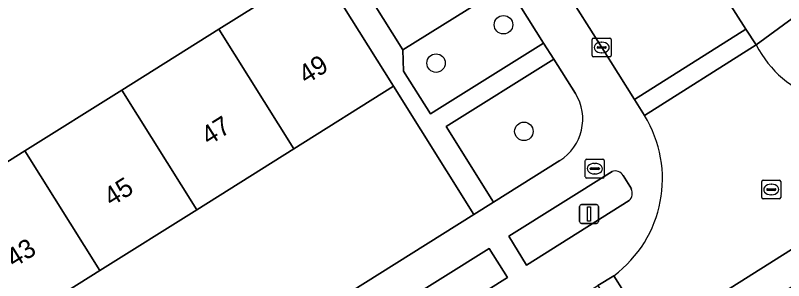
# Model space of a CAD drawing. Extents: x 160077 to 160948, y 386481 to 387498.
# Drawn here: x 160443.45 to 160484.07, y 387235.45 to 387249.48 of the extents above; entities that cross this region are included whole.
import ezdxf

# ---------------------------------------------------------------- set-up
doc = ezdxf.new("R2010")
doc.units = 0
for name, color, linetype in [('IMGEO_Boom', 7, 'Continuous'), ('IMGEO_Brandkraan', 7, 'Continuous'), ('IMGEO_Erf', 7, 'Continuous'), ('IMGEO_Groenvoorziening', 7, 'Continuous'), ('IMGEO_Kolk', 7, 'Continuous'), ('IMGEO_Lichtmast', 7, 'Continuous'), ('IMGEO_Pand', 7, 'Continuous'), ('IMGEO_Pand_nummerreeks', 7, 'Continuous'), ('IMGEO_Rijbaan_lokaal_gesloten', 7, 'Continuous'), ('IMGEO_Rijbaan_lokaal_open', 7, 'Continuous'), ('IMGEO_Rioolput', 7, 'Continuous'), ('IMGEO_Voetpad_open', 7, 'Continuous')]:
    doc.layers.add(name, color=color, linetype=linetype)

msp = doc.modelspace()

# ---------------------------------------------------------------- linework, layer by layer
at = {"layer": 'IMGEO_Boom'}
for centre in [(160469.256, 387248.98), (160465.692, 387246.952), (160470.336, 387243.344)]:
    msp.add_circle(centre, 0.489, dxfattribs=at)
at = {"layer": 'IMGEO_Brandkraan'}
for p, q in [((160473.583, 387240.946), (160473.583, 387241.798)), ((160473.658, 387241.872), (160474.51, 387241.872)), ((160474.071, 387241.652), (160474.096, 387241.652)), ((160474.584, 387241.798), (160474.584, 387240.946)), ((160473.842, 387241.366), (160473.842, 387241.378)), ((160474.28, 387241.329), (160473.882, 387241.329)), ((160473.885, 387241.415), (160474.283, 387241.415)), ((160474.326, 387241.378), (160474.326, 387241.366)), ((160474.51, 387240.872), (160473.658, 387240.872)), ((160474.094, 387241.092), (160474.069, 387241.092))]:
    msp.add_line(p, q, dxfattribs=at)
for points in [[(160473.583, 387240.946), (160473.583, 387241.798)], [(160473.658, 387241.872), (160474.51, 387241.872)], [(160474.584, 387241.798), (160474.584, 387240.946)], [(160474.51, 387240.872), (160473.658, 387240.872)]]:
    msp.add_lwpolyline(points, dxfattribs=at)
for centre, radius, start, end in [((160473.66, 387241.796), 0.0765, 91.552, 178.448), ((160473.66, 387241.796), 0.0765, 91.552, 178.448), ((160474.508, 387241.796), 0.0765, 1.552, 88.448), ((160474.508, 387241.796), 0.0765, 1.552, 88.448), ((160473.882, 387241.375), 0.0403, 85.8775, 175.7526), ((160473.879, 387241.365), 0.0366, 178.938, 274.7102), ((160474.283, 387241.372), 0.043, 264.8664, 352.4533), ((160474.287, 387241.377), 0.0386, 1.7309, 96.639), ((160473.66, 387240.948), 0.0765, 181.552, 268.448), ((160473.66, 387240.948), 0.0765, 181.552, 268.448), ((160474.508, 387240.948), 0.0765, 271.552, 358.448), ((160474.508, 387240.948), 0.0765, 271.552, 358.448)]:
    msp.add_arc(centre, radius, start, end, dxfattribs=at)
for centre, major_axis, ratio, start_param, end_param in [((160474.07, 387241.372), (-0.387, 0.002), 0.722429, 4.712389, 7.853982), ((160474.095, 387241.372), (-0.39, 0.002), 0.717154, 1.570796, 4.712389)]:
    msp.add_ellipse(centre, major_axis=major_axis, ratio=ratio, start_param=start_param, end_param=end_param, dxfattribs=at)
at = {"layer": 'IMGEO_Erf'}
for points in [[(160438.821, 387239.091), (160443.947, 387242.308), (160449.074, 387245.524), (160454.2, 387248.74), (160456.208, 387250), (160459.474, 387252.049), (160452.689, 387262.566), (160451.218, 387261.627), (160452.547, 387259.544), (160448.888, 387257.207), (160445.303, 387254.918), (160443.973, 387257.001), (160443.921, 387257.082), (160440.965, 387255.195)], [(160467.691, 387238.95), (160463.439, 387245.729), (160458.165, 387242.42), (160453.038, 387239.204), (160447.912, 387235.987), (160442.785, 387232.771), (160437.658, 387229.555), (160432.533, 387226.339), (160427.406, 387223.123), (160422.279, 387219.906), (160417.152, 387216.69), (160412.026, 387213.474), (160406.899, 387210.257), (160401.625, 387206.948), (160405.127, 387201.741)], [(160407.555, 387201.225), (160467.691, 387238.95)]]:
    msp.add_lwpolyline(points, dxfattribs=at)
at = {"layer": 'IMGEO_Groenvoorziening'}
for points in [[(160470.126, 387250), (160469.44, 387251.093), (160463.936, 387247.648), (160463.974, 387246.534), (160465.393, 387244.266), (160465.867, 387244.563), (160471.376, 387248.01)], [(160463.592, 387234.087), (160464.554, 387232.533), (160469.465, 387235.624), (160468.507, 387237.153)]]:
    msp.add_lwpolyline(points, close=True, dxfattribs=at)
for points in [[(160473.058, 387245.353), (160471.912, 387247.163), (160466.226, 387243.596), (160468.731, 387239.603), (160472.236, 387241.799)], [(160474.996, 387241.227), (160469.541, 387237.805)], [(160476.016, 387240.304), (160475.578, 387241.007)], [(160469.541, 387237.805), (160470.478, 387236.277), (160475.903, 387239.682)]]:
    msp.add_lwpolyline(points, dxfattribs=at)
for centre, radius, start, end in [((160470.863, 387243.989), 2.584, 302.0876, 31.8667), ((160475.154, 387240.764), 0.489, 29.7528, 108.8333), ((160475.516, 387240.074), 0.55, 314.6481, 24.7584)]:
    msp.add_arc(centre, radius, start, end, dxfattribs=at)
at = {"layer": 'IMGEO_Kolk'}
for p, q in [((160473.948, 387247.35), (160473.948, 387248.202)), ((160474.023, 387248.276), (160474.875, 387248.276)), ((160474.436, 387248.056), (160474.461, 387248.056)), ((160474.949, 387248.202), (160474.949, 387247.35)), ((160474.207, 387247.77), (160474.207, 387247.782)), ((160474.645, 387247.733), (160474.247, 387247.733)), ((160474.25, 387247.819), (160474.648, 387247.819)), ((160474.691, 387247.782), (160474.691, 387247.77)), ((160474.875, 387247.276), (160474.023, 387247.276)), ((160474.459, 387247.496), (160474.434, 387247.496))]:
    msp.add_line(p, q, dxfattribs=at)
for points in [[(160473.948, 387247.35), (160473.948, 387248.202)], [(160474.023, 387248.276), (160474.875, 387248.276)], [(160474.949, 387248.202), (160474.949, 387247.35)], [(160474.875, 387247.276), (160474.023, 387247.276)]]:
    msp.add_lwpolyline(points, dxfattribs=at)
for centre, radius, start, end in [((160474.025, 387248.2), 0.0765, 91.552, 178.448), ((160474.025, 387248.2), 0.0765, 91.552, 178.448), ((160474.873, 387248.2), 0.0765, 1.552, 88.448), ((160474.873, 387248.2), 0.0765, 1.552, 88.448), ((160474.247, 387247.779), 0.0403, 85.8775, 175.7526), ((160474.244, 387247.769), 0.0366, 178.938, 274.7102), ((160474.648, 387247.776), 0.043, 264.8664, 352.4533), ((160474.652, 387247.781), 0.0386, 1.7309, 96.639), ((160474.025, 387247.352), 0.0765, 181.552, 268.448), ((160474.025, 387247.352), 0.0765, 181.552, 268.448), ((160474.873, 387247.352), 0.0765, 271.552, 358.448), ((160474.873, 387247.352), 0.0765, 271.552, 358.448)]:
    msp.add_arc(centre, radius, start, end, dxfattribs=at)
for centre, major_axis, ratio, start_param, end_param in [((160474.435, 387247.776), (-0.387, 0.002), 0.722429, 4.712389, 7.853982), ((160474.46, 387247.776), (-0.39, 0.002), 0.717154, 1.570796, 4.712389)]:
    msp.add_ellipse(centre, major_axis=major_axis, ratio=ratio, start_param=start_param, end_param=end_param, dxfattribs=at)
at = {"layer": 'IMGEO_Lichtmast'}
for p, q in [((160473.281, 387238.575), (160473.281, 387239.375)), ((160473.281, 387239.375), (160473.281, 387238.575)), ((160473.381, 387239.475), (160474.171, 387239.475)), ((160474.171, 387239.475), (160473.381, 387239.475)), ((160474.271, 387239.375), (160474.271, 387238.575)), ((160474.271, 387238.575), (160474.271, 387239.375)), ((160474.171, 387238.475), (160473.381, 387238.475)), ((160473.381, 387238.475), (160474.171, 387238.475))]:
    msp.add_line(p, q, dxfattribs=at)
msp.add_lwpolyline([(160473.701, 387239.35), (160473.851, 387239.35), (160473.851, 387238.6), (160473.701, 387238.6), (160473.701, 387239.35)], dxfattribs=at)
for centre, start, end in [((160473.381, 387239.375), 90, 180), ((160473.381, 387239.375), 90, 180), ((160474.171, 387239.375), 0, 90), ((160474.171, 387239.375), 360, 90), ((160473.381, 387238.575), 180, 270), ((160473.381, 387238.575), 180, 270), ((160474.171, 387238.575), 270, 0), ((160474.171, 387238.575), 270, 0)]:
    msp.add_arc(centre, 0.1, start, end, dxfattribs=at)
at = {"layer": 'IMGEO_Pand'}
for points in [[(160469.44, 387251.093), (160469.313, 387251.296), (160467.838, 387253.653), (160462.334, 387250.208), (160463.936, 387247.648)], [(160458.165, 387242.42), (160463.439, 387245.729), (160460.76, 387250), (160459.474, 387252.049), (160456.208, 387250), (160454.2, 387248.74)], [(160454.2, 387248.74), (160449.074, 387245.524), (160453.038, 387239.204), (160458.165, 387242.42)], [(160447.912, 387235.987), (160453.038, 387239.204), (160449.074, 387245.524), (160443.947, 387242.308)], [(160443.947, 387242.308), (160438.821, 387239.091), (160442.785, 387232.771), (160447.912, 387235.987)]]:
    msp.add_lwpolyline(points, close=True, dxfattribs=at)
at = {"layer": 'IMGEO_Rijbaan_lokaal_gesloten'}
msp.add_lwpolyline([(160493.712, 387240.972), (160492.831, 387242.374), (160477.128, 387232.473), (160478.021, 387231.045)], close=True, dxfattribs=at)
at = {"layer": 'IMGEO_Rijbaan_lokaal_open'}
for points in [[(160454.544, 387279.719), (160463.8, 387264.904), (160472.539, 387250.825), (160474.449, 387247.776), (160476.176, 387245.021), (160482.077, 387248.744), (160480.89, 387250.608), (160479.886, 387252.225), (160472.444, 387264.366), (160463.176, 387278.973)], [(160482.621, 387247.91), (160476.71, 387244.182)], [(160475.088, 387235.715), (160477.128, 387232.473), (160492.831, 387242.374)]]:
    msp.add_lwpolyline(points, dxfattribs=at)
for points in [[(160482.621, 387247.91), (160482.077, 387248.744), (160476.176, 387245.021), (160476.71, 387244.182)], [(160475.088, 387235.715), (160474.253, 387235.192), (160475.133, 387233.755), (160476.287, 387231.935), (160477.162, 387230.526), (160478.021, 387231.045), (160477.128, 387232.473)]]:
    msp.add_lwpolyline(points, close=True, dxfattribs=at)
for centre, radius, start, end in [((160487.8, 387250.574), 5.824, 207.2196, 294.4722), ((160471.277, 387240.834), 6.382, 306.667, 31.6437)]:
    msp.add_arc(centre, radius, start, end, dxfattribs=at)
at = {"layer": 'IMGEO_Rioolput'}
for p, q in [((160482.988, 387240.769), (160483.84, 387240.769)), ((160482.913, 387239.843), (160482.913, 387240.695)), ((160483.401, 387240.549), (160483.426, 387240.549)), ((160483.914, 387240.695), (160483.914, 387239.843)), ((160483.172, 387240.263), (160483.172, 387240.275)), ((160483.61, 387240.226), (160483.212, 387240.226)), ((160483.215, 387240.312), (160483.613, 387240.312)), ((160483.424, 387239.989), (160483.399, 387239.989)), ((160483.656, 387240.275), (160483.656, 387240.263)), ((160483.84, 387239.769), (160482.988, 387239.769))]:
    msp.add_line(p, q, dxfattribs=at)
for points in [[(160482.988, 387240.769), (160483.84, 387240.769)], [(160482.913, 387239.843), (160482.913, 387240.695)], [(160483.914, 387240.695), (160483.914, 387239.843)], [(160483.84, 387239.769), (160482.988, 387239.769)]]:
    msp.add_lwpolyline(points, dxfattribs=at)
for centre, radius, start, end in [((160482.99, 387240.693), 0.0765, 91.552, 178.448), ((160482.99, 387240.693), 0.0765, 91.552, 178.448), ((160483.838, 387240.693), 0.0765, 1.552, 88.448), ((160483.838, 387240.693), 0.0765, 1.552, 88.448), ((160483.212, 387240.272), 0.0403, 85.8775, 175.7526), ((160483.209, 387240.262), 0.0366, 178.938, 274.7102), ((160483.613, 387240.269), 0.043, 264.8664, 352.4533), ((160483.617, 387240.274), 0.0386, 1.7309, 96.639), ((160482.99, 387239.845), 0.0765, 181.552, 268.448), ((160482.99, 387239.845), 0.0765, 181.552, 268.448), ((160483.838, 387239.845), 0.0765, 271.552, 358.448), ((160483.838, 387239.845), 0.0765, 271.552, 358.448)]:
    msp.add_arc(centre, radius, start, end, dxfattribs=at)
for centre, major_axis, ratio, start_param, end_param in [((160483.4, 387240.269), (-0.387, 0.002), 0.722429, 4.712389, 7.853982), ((160483.425, 387240.269), (-0.39, 0.002), 0.717154, 1.570796, 4.712389)]:
    msp.add_ellipse(centre, major_axis=major_axis, ratio=ratio, start_param=start_param, end_param=end_param, dxfattribs=at)
at = {"layer": 'IMGEO_Voetpad_open'}
for points in [[(160541.743, 387279.343), (160539.541, 387284.099), (160537.91, 387283.142), (160537.818, 387283.286), (160536.831, 387282.662), (160500, 387259.367), (160487.15, 387251.24), (160482.621, 387247.91)], [(160463.176, 387278.973), (160472.444, 387264.366), (160479.886, 387252.225), (160480.89, 387250.608), (160482.077, 387248.744), (160482.621, 387247.91), (160487.15, 387251.24)], [(160469.808, 387251.56), (160469.313, 387251.296), (160469.44, 387251.093), (160470.126, 387250), (160471.376, 387248.01), (160471.912, 387247.163), (160473.058, 387245.353)], [(160476.71, 387244.182), (160476.176, 387245.021), (160474.449, 387247.776), (160472.539, 387250.825)], [(160460.76, 387250), (160463.439, 387245.729), (160467.691, 387238.95), (160468.731, 387239.603), (160466.226, 387243.596), (160471.912, 387247.163), (160471.376, 387248.01), (160465.867, 387244.563), (160465.393, 387244.266), (160463.974, 387246.534), (160463.936, 387247.648), (160462.334, 387250.208)], [(160472.236, 387241.799), (160468.731, 387239.603), (160467.691, 387238.95), (160407.555, 387201.225), (160403.123, 387197.94), (160403.384, 387197.523)], [(160469.541, 387237.805), (160474.996, 387241.227)], [(160475.578, 387241.007), (160476.016, 387240.304)], [(160475.903, 387239.682), (160470.478, 387236.277), (160469.541, 387237.805)], [(160473.384, 387234.655), (160474.253, 387235.192), (160475.088, 387235.715)]]:
    msp.add_lwpolyline(points, dxfattribs=at)
msp.add_lwpolyline([(160468.507, 387237.153), (160469.465, 387235.624), (160464.554, 387232.533), (160463.592, 387234.087)], close=True, dxfattribs=at)
for centre, radius, start, end in [((160487.8, 387250.574), 5.824, 207.2196, 294.4722), ((160470.863, 387243.989), 2.584, 302.0876, 31.8667), ((160471.277, 387240.834), 6.382, 306.667, 31.6437), ((160475.154, 387240.764), 0.489, 29.7528, 108.8333), ((160475.516, 387240.074), 0.55, 314.6481, 24.7584)]:
    msp.add_arc(centre, radius, start, end, dxfattribs=at)

# ---------------------------------------------------------------- texts
at = {"layer": 'IMGEO_Pand_nummerreeks'}
for s, p in [('49', (160458.824, 387245.809)), ('47', (160453.673, 387242.577)), ('45', (160448.522, 387239.345)), ('43', (160443.371, 387236.113))]:
    msp.add_text(s, height=1, rotation=32.1034, dxfattribs=at).set_placement(p)

doc.saveas('drawing.dxf')
